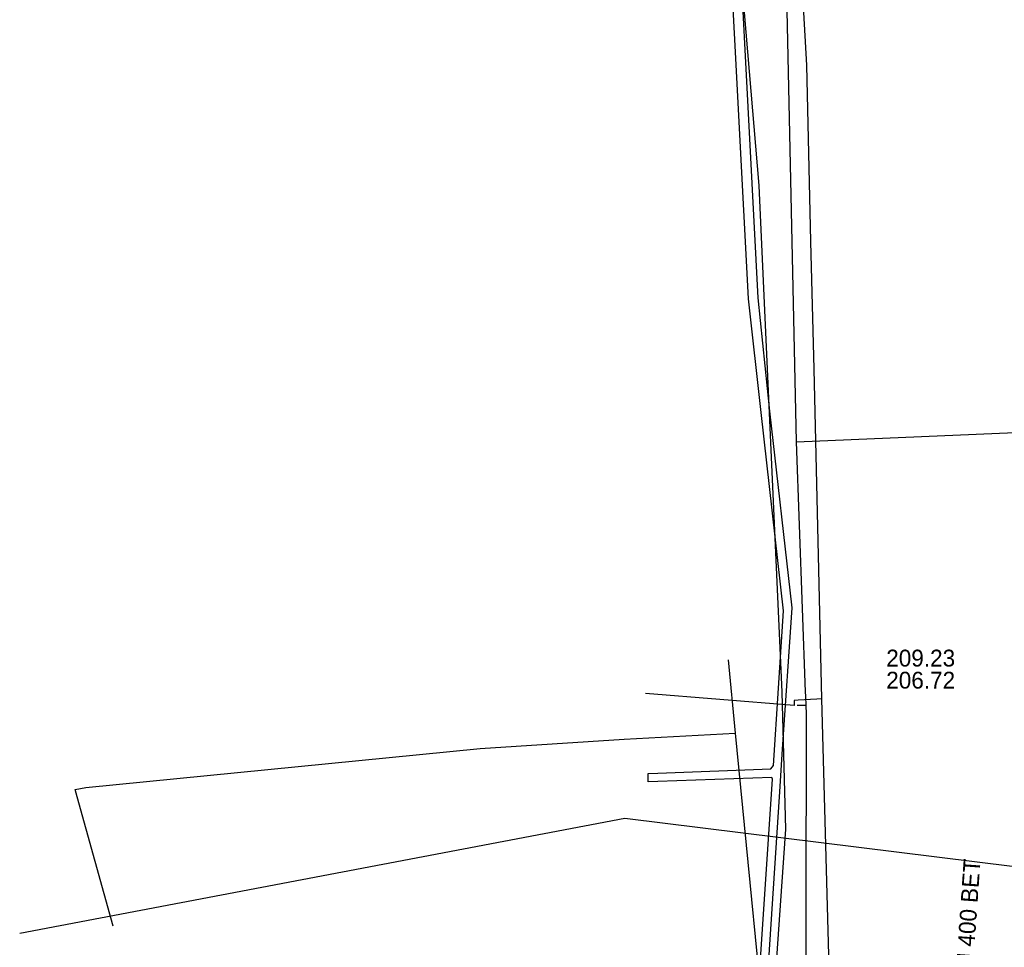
# Model space of a CAD drawing. Extents: x -596228 to -595156, y -1161235 to -1159373.
# Drawn here: x -595428.37 to -595381.63, y -1160774.27 to -1160730.2 of the extents above; entities that cross this region are included whole.
import ezdxf

# ---------------------------------------------------------------- set-up
doc = ezdxf.new("R2010")
doc.units = 0
for name, color, linetype in [('Vrstva 12', 7, 'Continuous'), ('Vrstva 14', 7, 'Continuous'), ('Vrstva 16', 7, 'Continuous'), ('Vrstva 19', 7, 'Continuous'), ('Vrstva 4', 7, 'Continuous'), ('Vrstva 42', 7, 'Continuous'), ('Vrstva 5', 7, 'Continuous'), ('Vrstva 9', 7, 'Continuous')]:
    doc.layers.add(name, color=color, linetype=linetype)

msp = doc.modelspace()

# ---------------------------------------------------------------- linework, layer by layer
at = {"layer": 'Vrstva 12'}
msp.add_lwpolyline([(-595391.73, -1160797.15), (-595393.53, -1160790.65), (-595392, -1160768.65), (-595392.17, -1160762.15), (-595393.27, -1160738.08), (-595395.42, -1160712.66)], dxfattribs=at)
at = {"layer": 'Vrstva 14'}
msp.add_lwpolyline([(-595376.306, -1160771.081), (-595376.552, -1160771.04), (-595377.425, -1160770.909), (-595399.638, -1160768.145), (-595428.371, -1160773.614)], dxfattribs=at)
at = {"layer": 'Vrstva 16'}
msp.add_line((-595391.03, -1160762.78), (-595391.46, -1160762.79), dxfattribs=at)
for points in [[(-595391.495, -1160750.254), (-595392.29, -1160713.66), (-595391.78, -1160712.81), (-595391.169, -1160711.763), (-595391.08, -1160711.61), (-595390.62, -1160710.84), (-595389.81, -1160710.56), (-595351.48, -1160698.37), (-595374.59, -1160618.59), (-595374.98, -1160617.04), (-595376.36, -1160612.52), (-595376.56, -1160612.21), (-595376.96, -1160612.24), (-595378.92, -1160612.81), (-595414.64, -1160624.38)], [(-595391.495, -1160750.254), (-595360.707, -1160748.948), (-595358.13, -1160748.839)], [(-595391.08, -1160797.86), (-595391.014, -1160763.76), (-595391.02, -1160763.18), (-595391.03, -1160762.78), (-595391.05, -1160762.34), (-595391.072, -1160762.138), (-595391.495, -1160750.254)]]:
    msp.add_lwpolyline(points, dxfattribs=at)
at = {"layer": 'Vrstva 19'}
msp.add_line((-595391.61, -1160762.78), (-595398.66, -1160762.22), dxfattribs=at)
for points in [[(-595389.404, -1160802.393), (-595389.5, -1160798.11), (-595389.515, -1160797.422), (-595389.9, -1160779.84), (-595389.83, -1160779.44), (-595389.83, -1160779.29), (-595389.84, -1160778.69), (-595390.29, -1160762.47), (-595390.66, -1160746.8), (-595390.803, -1160740.734), (-595391, -1160732.37), (-595392.01, -1160714.52)], [(-595390.29, -1160762.47), (-595390.52, -1160762.48), (-595391.42, -1160762.53), (-595391.61, -1160762.54), (-595391.61, -1160762.78)]]:
    msp.add_lwpolyline(points, dxfattribs=at)
at = {"layer": 'Vrstva 42'}
for points in [[(-595392.981, -1160775.879), (-595392.96, -1160775.586), (-595392.809, -1160774.871), (-595392.306, -1160767.127), (-595392.152, -1160764.854), (-595391.699, -1160758.146), (-595392.757, -1160748.803), (-595393.318, -1160743.424), (-595394.619, -1160718.319), (-595394.827, -1160714.688), (-595394.419, -1160714.064), (-595391.865, -1160712.692), (-595379.095, -1160708.846)], [(-595393.181, -1160775.883), (-595393.16, -1160775.573), (-595393.199, -1160774.839), (-595392.631, -1160766.275), (-595392.663, -1160766.21), (-595398.08, -1160766.397), (-595398.537, -1160766.407), (-595398.537, -1160766.207), (-595398.537, -1160766.007), (-595398.08, -1160765.997), (-595392.714, -1160765.797), (-595392.589, -1160765.626), (-595392.116, -1160758.279), (-595393.169, -1160748.862), (-595393.767, -1160743.464), (-595395.101, -1160718.222), (-595395.59, -1160714.754), (-595396.444, -1160714.03), (-595397.03, -1160713.242)]]:
    msp.add_lwpolyline(points, dxfattribs=at)
at = {"layer": 'Vrstva 5'}
for p, q in [((-595399.68, -1160764.38), (-595394.4, -1160764.1)), ((-595423.94, -1160773.26), (-595425.646, -1160767.115)), ((-595423.94, -1160773.26), (-595425.646, -1160767.115))]:
    msp.add_line(p, q, dxfattribs=at)
msp.add_lwpolyline([(-595425.646, -1160767.115), (-595425.73, -1160766.77), (-595425.236, -1160766.682), (-595406.51, -1160764.82), (-595399.68, -1160764.38)], dxfattribs=at)
at = {"layer": 'Vrstva 9'}
msp.add_lwpolyline([(-595394.74, -1160760.61), (-595394.4, -1160764.1), (-595392.68, -1160781.67), (-595390.37, -1160805.25)], dxfattribs=at)

# ---------------------------------------------------------------- texts
at = {"layer": 'Vrstva 4'}
for s, p in [('209.23', (-595387.231, -1160760.93)), ('206.72', (-595387.231, -1160761.98))]:
    msp.add_text(s, height=0.8, dxfattribs=at).set_placement(p)
msp.add_text('DN 400 BET', height=0.8, rotation=86, dxfattribs=at).set_placement((-595383.171, -1160776.095))

doc.saveas('drawing.dxf')
